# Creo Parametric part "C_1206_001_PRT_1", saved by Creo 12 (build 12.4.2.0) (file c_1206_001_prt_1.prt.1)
Units: Custom; MM, KILOGRAM, SECS

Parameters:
  PTC_WM_ITERATION = "0"
  PTC_WM_VERSION = "-.0"
  PTC_WM_LIFECYCLE_STATE = "In Work"
  PTC_WM_LIFECYCLE = "MO_CADDocument"
  PTC_WM_CREATED_BY = "Maximilian Roepper (Z0017RMS: MO)"
  PTC_WM_CREATED_ON = "18-Sep-26 11:36:42 AM"
  PTC_WM_MODIFIED_BY = "Maximilian Roepper (Z0017RMS: MO)"
  PTC_WM_MODIFIED_ON = "18-Sep-26 11:36:46 AM"
  PDMLINKNUMBER = "PDM000071454800"
  PTC_WM_NAME = "c_1206_001_prt_1.prt"
  PTC_WM_NUMBER = "PDM000071454800"

Other parameters: WEIGHT, WEIGHT_FACTOR, WEIGHT_ADD, _MASS_TEMP, _DIFF_TEMP, MC_ERRORS, SUPPLIER

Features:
  1. coordinate system
  2. datum plane "PRT_YZ"
  3. datum plane "PRT_XY"
  4. datum plane "PRT_XZ"
  5. coordinate system
  6. datum axis
  7. datum axis
  8. datum axis
  9. coordinate system
  10. imported feature
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
Other named items: PRT, SIEMENS_MO, DRW_VIEW_ORG, PRT_X, PRT_Y, PRT_Z, CS0, ROUGH_GROB

Layers: 00_STD_CSYS-KSYS, 01_STD_PLANES-EBENEN, 02_STD_AXES-ACHSEN, 03_STD_CSYS-KSYS, 24_IMPORT_FEAT-IMPORT_KE

Surfaces: 16 plane, 12 cylinder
